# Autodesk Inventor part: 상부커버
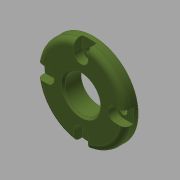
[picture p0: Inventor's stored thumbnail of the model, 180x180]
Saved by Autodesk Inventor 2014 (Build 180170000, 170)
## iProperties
Created: 2019-01
Part Number: 상부커버
Material: 알루미늄 6061
Document SubType Name: Modeling
Designer: mduedu
Density: 2.71 g/cm^3
Appearance: 올리브 녹색
Mass: 28.8858 g
Surface Area: 53.2237 cm^2
Volume: 10.659 cm^3
Author: mduedu
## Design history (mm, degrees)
sketch "스케치1"
  geometry: L1 (0, 0)-(7, 0); L2 (7, 0)-(7, 25); L3 (7, 25)-(0, 25); L4 (0, 25)-(0, 0); L5 (7, 0)-(10, 0); L6 (10, 0)-(10, 14); L7 (10, 14)-(7, 14); L8 (7, 14)-(7, 0)
  constraints: 16 end point, 4 parallel, 2 horizontal, 2 perpendicular
  dimensions: "d0" = 50 diameter of L3 L1; "d2" = 10 distance between parallel lines of L6 L4; "d3" = 7 distance of L2.end L3.end; "d4" = 28 diameter of L7 L5
revolve "회전1" sketch "스케치1" stored, may be unused: angle "d5" = 90 deg
sketch "스케치2"
  geometry: C1 r 10 at (0, 0); 1 further point
  constraints: 1 centre point, 1 coincident
  dimensions: "d6" = 20 diameter of C1
extrude "돌출1" cut sketch "스케치2" stored distance "d7" = 10; taper "d8" = 0 deg
chamfer "모따기1" distance "d9" = 1; stored, may be unused: second distance "d10" = 2, angle "d11" = 45 deg
fillet "모깎기1" dims "d12" = 3
sketch "스케치3" dims "d13" = 38
  geometry: 6 further points
  constraints: 2 vertical alignment, 1 coincident, 7 other
  dimensions: "d16" = 360 deg dimension on point (0, 0) point (0, 19) (derived)
chamfer "모따기2" distance "d18" = 1; stored, may be unused: second distance "d19" = 2, angle "d20" = 45 deg
sketch "스케치4"
  geometry: 4 further points
  constraints: 4 other
hole "구멍1" sketch "스케치4" at (-19, 0), (0, -19), (19, 0), (0, 19) diameter "d21" = 4.5; stored, may be unused: countersink angle "d25" = 90 deg, drill point angle "d27" = 0 deg; dims "d22" = 6, "d23" = 8, "d24" = 4.6, "d26" = 8
sketch "스케치5"
  geometry: L1 (-4, 0)-(-4, 5.678); L2 (4, 0)-(4, 5.678); A1 r 4 centre (0, 0) between (-2.841, 2.816) and (2.841, 2.816) reference; A2 r 25 centre (0, -19) between (-4, 5.678) and (4, 5.678) reference; A3 r 4 centre (0, 0) between (-4, 0) and (4, 0); A4 r 25 centre (0, -19) between (4, 5.678) and (-4, 5.678); A5 r 4 centre (0, 0) between (4, 0) and (-4, 0); 1 further point
  constraints: 10 point on circle, 4 end point, 3 centre point, 2 coincident, 2 tangent, 1 parallel, 1 vertical
extrude "돌출2" cut sketch "스케치5" stored distance "d28" = 10; taper "d29" = 0 deg
node "솔리드1"
pattern_circular "원형 패턴1" dims angle "d31" = 360 deg
